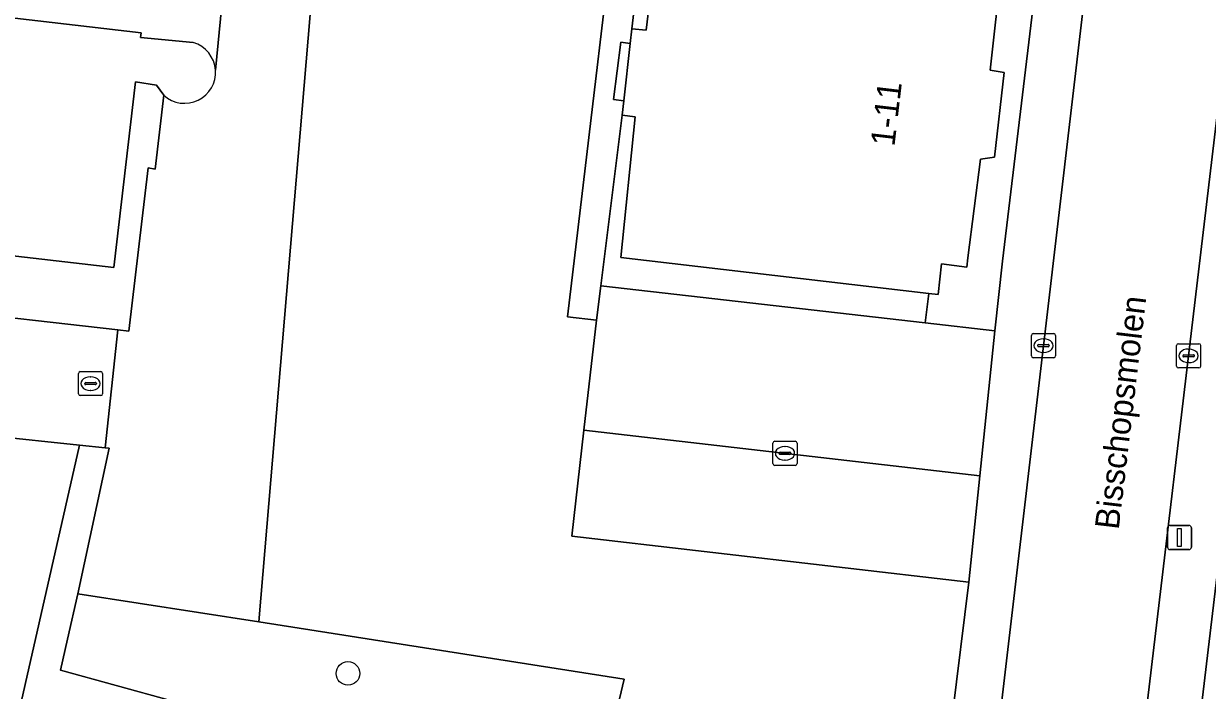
# Model space of a CAD drawing. Extents: x 161241 to 161758, y 384138 to 384885.
# Drawn here: x 161336.04 to 161385.2, y 384315.21 to 384342.9 of the extents above; entities that cross this region are included whole.
import ezdxf

# ---------------------------------------------------------------- set-up
doc = ezdxf.new("R2010")
doc.units = 0
for name, color, linetype in [('IMGEO_Boom', 7, 'Continuous'), ('IMGEO_Erf', 7, 'Continuous'), ('IMGEO_Groenvoorziening', 7, 'Continuous'), ('IMGEO_Kolk', 7, 'Continuous'), ('IMGEO_Lichtmast', 7, 'Continuous'), ('IMGEO_Openbare_ruimte_label', 7, 'Continuous'), ('IMGEO_Pand', 7, 'Continuous'), ('IMGEO_Pand_nummerreeks', 7, 'Continuous'), ('IMGEO_Parkeervlak_open', 7, 'Continuous'), ('IMGEO_Rijbaan_lokaal_open', 7, 'Continuous'), ('IMGEO_Rioolput', 7, 'Continuous'), ('IMGEO_Voetpad_open', 7, 'Continuous')]:
    doc.layers.add(name, color=color, linetype=linetype)

msp = doc.modelspace()

# ---------------------------------------------------------------- linework, layer by layer
at = {"layer": 'IMGEO_Boom'}
msp.add_circle((161349.508, 384315.915), 0.489, dxfattribs=at)
at = {"layer": 'IMGEO_Erf'}
for points in [[(161318.52, 384465.21), (161310.988, 384400.64), (161311.596, 384400.569), (161310.981, 384395.295), (161318.645, 384394.401), (161313.564, 384350.843), (161307.345, 384351.569), (161306.77, 384346.638), (161308.845, 384346.396), (161308.829, 384346.258), (161340.917, 384342.515), (161340.895, 384342.324), (161343.078, 384342.11)], [(161344.007, 384340.964), (161345.314, 384354.343), (161329.206, 384356.211), (161329.442, 384358.011), (161337.531, 384426.972)]]:
    msp.add_lwpolyline(points, dxfattribs=at)
msp.add_lwpolyline([(161378.13, 384345.016), (161378.443, 384347.869), (161375.567, 384348.189), (161375.428, 384346.989), (161375.816, 384346.944), (161375.67, 384345.674), (161376.693, 384345.564), (161376.653, 384345.204), (161376.183, 384340.963), (161376.768, 384340.873), (161376.359, 384337.347), (161375.779, 384337.27), (161375.26, 384333.173), (161375.211, 384332.782), (161374.16, 384332.92), (161374.023, 384331.651), (161373.636, 384331.696), (161373.482, 384330.476), (161376.372, 384330.142), (161376.699, 384333.039)], close=True, dxfattribs=at)
msp.add_arc((161342.719, 384340.869), 1.291, 4.1985, 73.8611, dxfattribs=at)
at = {"layer": 'IMGEO_Groenvoorziening'}
for points in [[(161341.863, 384339.923), (161341.496, 384336.855), (161341.203, 384336.905), (161340.408, 384330.125), (161339.947, 384330.177), (161339.428, 384325.279), (161339.593, 384325.267), (161338.281, 384319.226), (161345.806, 384318.051), (161348.839, 384353.935), (161345.314, 384354.343), (161344.007, 384340.964)], [(161359.736, 384305.395), (161365.529, 384304.017), (161372.24, 384302.407), (161373.142, 384302.222), (161374.439, 384312.732), (161374.623, 384314.221), (161375.299, 384319.702), (161358.812, 384321.618), (161359.31, 384326.016), (161359.827, 384330.585), (161358.63, 384330.717), (161361.21, 384352.499), (161349.287, 384353.883), (161348.839, 384353.935), (161345.806, 384318.051), (161360.974, 384315.683), (161359.706, 384310.307), (161358.781, 384307.069)], [(161328.866, 384324.519), (161328.421, 384321.506), (161295.885, 384325.211), (161295.467, 384325.102), (161295.374, 384323.02), (161335.524, 384312.89), (161338.358, 384325.391), (161331.006, 384326.163)], [(161386.343, 384326.184), (161383.222, 384299.937), (161383.058, 384298.581), (161401.355, 384293.157)]]:
    msp.add_lwpolyline(points, dxfattribs=at)
msp.add_lwpolyline([(161337.862, 384317.338), (161337.568, 384316.046), (161342.197, 384314.772), (161343.987, 384314.34), (161359.706, 384310.307), (161360.974, 384315.683), (161345.806, 384318.051), (161338.281, 384319.226)], close=True, dxfattribs=at)
msp.add_arc((161342.727, 384340.873), 1.284, 227.7279, 4.0691, dxfattribs=at)
at = {"layer": 'IMGEO_Kolk'}
for p, q in [((161377.896, 384329.1), (161377.896, 384329.952)), ((161377.971, 384330.026), (161378.823, 384330.026)), ((161378.897, 384329.952), (161378.897, 384329.1)), ((161378.155, 384329.52), (161378.155, 384329.532)), ((161378.593, 384329.483), (161378.195, 384329.483)), ((161378.198, 384329.569), (161378.596, 384329.569)), ((161378.384, 384329.806), (161378.409, 384329.806)), ((161378.639, 384329.532), (161378.639, 384329.52)), ((161383.924, 384328.677), (161383.924, 384329.529)), ((161383.999, 384329.603), (161384.851, 384329.603)), ((161384.412, 384329.383), (161384.437, 384329.383)), ((161384.925, 384329.529), (161384.925, 384328.677)), ((161378.823, 384329.026), (161377.971, 384329.026)), ((161378.407, 384329.246), (161378.382, 384329.246)), ((161384.183, 384329.097), (161384.183, 384329.109)), ((161384.621, 384329.06), (161384.223, 384329.06)), ((161384.226, 384329.146), (161384.624, 384329.146)), ((161384.667, 384329.109), (161384.667, 384329.097)), ((161384.851, 384328.603), (161383.999, 384328.603)), ((161384.435, 384328.823), (161384.41, 384328.823)), ((161367.159, 384324.629), (161367.159, 384325.481)), ((161367.234, 384325.555), (161368.086, 384325.555)), ((161368.16, 384325.481), (161368.16, 384324.629)), ((161367.418, 384325.049), (161367.418, 384325.061)), ((161367.856, 384325.012), (161367.458, 384325.012)), ((161367.461, 384325.098), (161367.859, 384325.098)), ((161367.647, 384325.335), (161367.672, 384325.335)), ((161367.902, 384325.061), (161367.902, 384325.049)), ((161368.086, 384324.555), (161367.234, 384324.555)), ((161367.67, 384324.775), (161367.645, 384324.775))]:
    msp.add_line(p, q, dxfattribs=at)
for points in [[(161377.896, 384329.1), (161377.896, 384329.952)], [(161377.971, 384330.026), (161378.823, 384330.026)], [(161378.897, 384329.952), (161378.897, 384329.1)], [(161383.924, 384328.677), (161383.924, 384329.529)], [(161383.999, 384329.603), (161384.851, 384329.603)], [(161384.925, 384329.529), (161384.925, 384328.677)], [(161378.823, 384329.026), (161377.971, 384329.026)], [(161384.851, 384328.603), (161383.999, 384328.603)], [(161367.159, 384324.629), (161367.159, 384325.481)], [(161367.234, 384325.555), (161368.086, 384325.555)], [(161368.16, 384325.481), (161368.16, 384324.629)], [(161368.086, 384324.555), (161367.234, 384324.555)]]:
    msp.add_lwpolyline(points, dxfattribs=at)
for centre, radius, start, end in [((161377.973, 384329.95), 0.0765, 91.552, 178.448), ((161377.973, 384329.95), 0.0765, 91.552, 178.448), ((161378.821, 384329.95), 0.0765, 1.552, 88.448), ((161378.821, 384329.95), 0.0765, 1.552, 88.448), ((161378.195, 384329.529), 0.0403, 85.8775, 175.7526), ((161378.192, 384329.519), 0.0366, 178.938, 274.7102), ((161378.596, 384329.526), 0.043, 264.8664, 352.4533), ((161378.6, 384329.531), 0.0386, 1.7309, 96.639), ((161384.001, 384329.527), 0.0765, 91.552, 178.448), ((161384.001, 384329.527), 0.0765, 91.552, 178.448), ((161384.849, 384329.527), 0.0765, 1.552, 88.448), ((161384.849, 384329.527), 0.0765, 1.552, 88.448), ((161377.973, 384329.102), 0.0765, 181.552, 268.448), ((161377.973, 384329.102), 0.0765, 181.552, 268.448), ((161378.821, 384329.102), 0.0765, 271.552, 358.448), ((161378.821, 384329.102), 0.0765, 271.552, 358.448), ((161384.223, 384329.106), 0.0403, 85.8775, 175.7526), ((161384.22, 384329.096), 0.0366, 178.938, 274.7102), ((161384.624, 384329.103), 0.043, 264.8664, 352.4533), ((161384.628, 384329.108), 0.0386, 1.7309, 96.639), ((161384.001, 384328.679), 0.0765, 181.552, 268.448), ((161384.001, 384328.679), 0.0765, 181.552, 268.448), ((161384.849, 384328.679), 0.0765, 271.552, 358.448), ((161384.849, 384328.679), 0.0765, 271.552, 358.448), ((161367.236, 384325.479), 0.0765, 91.552, 178.448), ((161367.236, 384325.479), 0.0765, 91.552, 178.448), ((161368.084, 384325.479), 0.0765, 1.552, 88.448), ((161368.084, 384325.479), 0.0765, 1.552, 88.448), ((161367.458, 384325.058), 0.0403, 85.8775, 175.7526), ((161367.455, 384325.048), 0.0366, 178.938, 274.7102), ((161367.859, 384325.055), 0.043, 264.8664, 352.4533), ((161367.863, 384325.06), 0.0386, 1.7309, 96.639), ((161367.236, 384324.631), 0.0765, 181.552, 268.448), ((161367.236, 384324.631), 0.0765, 181.552, 268.448), ((161368.084, 384324.631), 0.0765, 271.552, 358.448), ((161368.084, 384324.631), 0.0765, 271.552, 358.448)]:
    msp.add_arc(centre, radius, start, end, dxfattribs=at)
for centre, major_axis, ratio, start_param, end_param in [((161378.383, 384329.526), (-0.387, 0.002), 0.722429, 4.712389, 7.853982), ((161378.408, 384329.526), (-0.39, 0.002), 0.717154, 1.570796, 4.712389), ((161384.411, 384329.103), (-0.387, 0.002), 0.722429, 4.712389, 7.853982), ((161384.436, 384329.103), (-0.39, 0.002), 0.717154, 1.570796, 4.712389), ((161367.646, 384325.055), (-0.387, 0.002), 0.722429, 4.712389, 7.853982), ((161367.671, 384325.055), (-0.39, 0.002), 0.717154, 1.570796, 4.712389)]:
    msp.add_ellipse(centre, major_axis=major_axis, ratio=ratio, start_param=start_param, end_param=end_param, dxfattribs=at)
at = {"layer": 'IMGEO_Lichtmast'}
for p, q in [((161383.548, 384321.16), (161383.548, 384321.96)), ((161383.548, 384321.96), (161383.548, 384321.16)), ((161383.648, 384322.06), (161384.438, 384322.06)), ((161384.438, 384322.06), (161383.648, 384322.06)), ((161384.538, 384321.96), (161384.538, 384321.16)), ((161384.538, 384321.16), (161384.538, 384321.96)), ((161384.438, 384321.06), (161383.648, 384321.06)), ((161383.648, 384321.06), (161384.438, 384321.06))]:
    msp.add_line(p, q, dxfattribs=at)
msp.add_lwpolyline([(161383.968, 384321.935), (161384.118, 384321.935), (161384.118, 384321.185), (161383.968, 384321.185), (161383.968, 384321.935)], dxfattribs=at)
for centre, start, end in [((161383.648, 384321.96), 90, 180), ((161383.648, 384321.96), 90, 180), ((161384.438, 384321.96), 0, 90), ((161384.438, 384321.96), 360, 90), ((161383.648, 384321.16), 180, 270), ((161383.648, 384321.16), 180, 270), ((161384.438, 384321.16), 270, 0), ((161384.438, 384321.16), 270, 0)]:
    msp.add_arc(centre, 0.1, start, end, dxfattribs=at)
at = {"layer": 'IMGEO_Pand'}
for points in [[(161343.078, 384342.11), (161340.895, 384342.324), (161340.917, 384342.515), (161308.829, 384346.258), (161308.845, 384346.396), (161306.77, 384346.638), (161307.345, 384351.569), (161313.564, 384350.843), (161318.645, 384394.401), (161310.981, 384395.295), (161311.596, 384400.569), (161310.988, 384400.64), (161318.52, 384465.21)], [(161297.572, 384347.701), (161296.472, 384337.807), (161301.751, 384337.193), (161313.085, 384335.875), (161323.181, 384334.701), (161334.383, 384333.399), (161339.781, 384332.771), (161340.681, 384340.487), (161341.556, 384340.345), (161341.863, 384339.923)]]:
    msp.add_lwpolyline(points, dxfattribs=at)
msp.add_lwpolyline([(161360.894, 384339.097), (161361.432, 384339.026), (161360.848, 384333.186), (161373.636, 384331.696), (161374.023, 384331.651), (161374.16, 384332.92), (161375.211, 384332.782), (161375.26, 384333.173), (161375.779, 384337.27), (161376.359, 384337.347), (161376.768, 384340.873), (161376.183, 384340.963), (161376.653, 384345.204), (161376.693, 384345.564), (161375.67, 384345.674), (161375.816, 384346.944), (161375.428, 384346.989), (161362.595, 384348.491), (161361.888, 384342.626), (161361.303, 384342.682), (161361.233, 384342.067), (161360.963, 384339.699)], close=True, dxfattribs=at)
for centre, radius, start, end in [((161342.719, 384340.869), 1.291, 4.1985, 73.8611), ((161342.727, 384340.873), 1.284, 227.7279, 4.0691)]:
    msp.add_arc(centre, radius, start, end, dxfattribs=at)
at = {"layer": 'IMGEO_Parkeervlak_open'}
msp.add_lwpolyline([(161358.812, 384321.618), (161375.299, 384319.702), (161375.754, 384324.126), (161359.31, 384326.016)], close=True, dxfattribs=at)
at = {"layer": 'IMGEO_Rijbaan_lokaal_open'}
for points in [[(161388.102, 384360.026), (161388.45, 384362.95), (161388.474, 384363.189), (161382.385, 384363.904), (161382.338, 384363.509), (161382.029, 384360.807), (161380.816, 384350.22), (161380.553, 384347.92), (161375.412, 384304.063), (161375.385, 384303.831), (161374.158, 384293.356), (161374.069, 384292.593), (161373.523, 384287.939), (161379.384, 384287.252), (161380.279, 384294.53), (161380.712, 384297.896), (161380.767, 384298.362), (161386.821, 384349.251)], [(161359.31, 384326.016), (161375.754, 384324.126), (161376.372, 384330.142), (161373.482, 384330.476), (161360.016, 384332.008), (161359.827, 384330.585)]]:
    msp.add_lwpolyline(points, close=True, dxfattribs=at)
msp.add_lwpolyline([(161294.386, 384330.412), (161294.515, 384330.402), (161294.785, 384330.366), (161299.909, 384329.775), (161313.921, 384328.174), (161331.006, 384326.163), (161338.358, 384325.391), (161339.428, 384325.279), (161339.947, 384330.177), (161317.215, 384332.754)], dxfattribs=at)
at = {"layer": 'IMGEO_Rioolput'}
for p, q in [((161338.314, 384327.524), (161338.314, 384328.376)), ((161338.389, 384328.45), (161339.241, 384328.45)), ((161339.315, 384328.376), (161339.315, 384327.524)), ((161338.573, 384327.944), (161338.573, 384327.956)), ((161339.011, 384327.907), (161338.613, 384327.907)), ((161338.616, 384327.993), (161339.014, 384327.993)), ((161338.802, 384328.23), (161338.827, 384328.23)), ((161339.057, 384327.956), (161339.057, 384327.944)), ((161339.241, 384327.45), (161338.389, 384327.45)), ((161338.825, 384327.67), (161338.8, 384327.67))]:
    msp.add_line(p, q, dxfattribs=at)
for points in [[(161338.314, 384327.524), (161338.314, 384328.376)], [(161338.389, 384328.45), (161339.241, 384328.45)], [(161339.315, 384328.376), (161339.315, 384327.524)], [(161339.241, 384327.45), (161338.389, 384327.45)]]:
    msp.add_lwpolyline(points, dxfattribs=at)
for centre, radius, start, end in [((161338.391, 384328.374), 0.0765, 91.552, 178.448), ((161338.391, 384328.374), 0.0765, 91.552, 178.448), ((161339.239, 384328.374), 0.0765, 1.552, 88.448), ((161339.239, 384328.374), 0.0765, 1.552, 88.448), ((161338.613, 384327.953), 0.0403, 85.8775, 175.7526), ((161338.61, 384327.943), 0.0366, 178.938, 274.7102), ((161339.014, 384327.95), 0.043, 264.8664, 352.4533), ((161339.018, 384327.955), 0.0386, 1.7309, 96.639), ((161338.391, 384327.526), 0.0765, 181.552, 268.448), ((161338.391, 384327.526), 0.0765, 181.552, 268.448), ((161339.239, 384327.526), 0.0765, 271.552, 358.448), ((161339.239, 384327.526), 0.0765, 271.552, 358.448)]:
    msp.add_arc(centre, radius, start, end, dxfattribs=at)
for centre, major_axis, ratio, start_param, end_param in [((161338.801, 384327.95), (-0.387, 0.002), 0.722429, 4.712389, 7.853982), ((161338.826, 384327.95), (-0.39, 0.002), 0.717154, 1.570796, 4.712389)]:
    msp.add_ellipse(centre, major_axis=major_axis, ratio=ratio, start_param=start_param, end_param=end_param, dxfattribs=at)
at = {"layer": 'IMGEO_Voetpad_open'}
for points in [[(161388.778, 384366.166), (161388.754, 384365.965), (161388.474, 384363.189), (161388.45, 384362.95), (161388.102, 384360.026), (161388.591, 384359.969), (161387.33, 384349.191), (161386.821, 384349.251), (161380.767, 384298.362), (161381.263, 384298.301), (161383.002, 384298.118), (161383.058, 384298.581), (161383.222, 384299.937), (161386.343, 384326.184), (161389.324, 384351.032), (161391.147, 384350.82), (161391.7, 384355.381), (161392.099, 384359.279), (161393.196, 384368.833)], [(161372.354, 384277.971), (161373.201, 384285.193), (161373.523, 384287.939), (161374.069, 384292.593), (161373.573, 384292.651), (161374.916, 384304.121), (161375.412, 384304.063), (161380.553, 384347.92), (161380.816, 384350.22), (161380.32, 384350.276), (161381.533, 384360.863), (161382.029, 384360.807), (161382.338, 384363.509), (161382.385, 384363.904), (161382.703, 384366.584)], [(161292.774, 384346.569), (161292.073, 384340.641), (161296.063, 384335.287), (161317.215, 384332.754), (161339.947, 384330.177), (161340.408, 384330.125), (161341.203, 384336.905), (161341.496, 384336.855), (161341.863, 384339.923), (161341.556, 384340.345), (161340.681, 384340.487), (161339.781, 384332.771), (161334.383, 384333.399), (161334.223, 384332.033), (161323.022, 384333.336), (161323.181, 384334.701), (161313.085, 384335.875), (161312.912, 384334.391), (161301.582, 384335.71), (161301.751, 384337.193), (161296.472, 384337.807), (161297.572, 384347.701)], [(161378.13, 384345.016), (161376.699, 384333.039), (161376.372, 384330.142), (161375.754, 384324.126), (161375.299, 384319.702), (161374.623, 384314.221), (161374.439, 384312.732), (161373.142, 384302.222), (161372.24, 384302.407), (161371.443, 384296.485), (161366.499, 384297.676), (161366.059, 384297.781), (161365.595, 384295.806), (161365.649, 384294.31), (161365.768, 384291), (161365.862, 384288.743), (161365.967, 384286.221), (161366.223, 384280.106)], [(161341.253, 384311.101), (161342.197, 384314.772), (161337.568, 384316.046), (161337.862, 384317.338), (161338.281, 384319.226), (161339.593, 384325.267), (161339.428, 384325.279), (161338.358, 384325.391), (161335.524, 384312.89), (161295.374, 384323.02), (161295.467, 384325.102), (161295.885, 384325.211), (161296.198, 384328.486)]]:
    msp.add_lwpolyline(points, dxfattribs=at)
for points in [[(161358.63, 384330.717), (161359.827, 384330.585), (161360.016, 384332.008), (161360.894, 384339.097), (161360.963, 384339.699), (161360.54, 384339.747), (161360.839, 384342.122), (161361.233, 384342.067), (161361.303, 384342.682), (161361.988, 384348.574), (161362.433, 384352.359), (161361.21, 384352.499)], [(161361.303, 384342.682), (161361.888, 384342.626), (161362.595, 384348.491), (161361.988, 384348.574)], [(161360.963, 384339.699), (161361.233, 384342.067), (161360.839, 384342.122), (161360.54, 384339.747)], [(161360.016, 384332.008), (161373.482, 384330.476), (161373.636, 384331.696), (161360.848, 384333.186), (161361.432, 384339.026), (161360.894, 384339.097)]]:
    msp.add_lwpolyline(points, close=True, dxfattribs=at)

# ---------------------------------------------------------------- texts
at = {"layer": 'IMGEO_Openbare_ruimte_label'}
msp.add_text('Bisschopsmolen', height=1, rotation=83.2232, dxfattribs=at).set_placement((161381.519, 384321.859))
at = {"layer": 'IMGEO_Pand_nummerreeks'}
msp.add_text('1-11', height=1, rotation=83.313, dxfattribs=at).set_placement((161372.204, 384337.774))

doc.saveas('drawing.dxf')
